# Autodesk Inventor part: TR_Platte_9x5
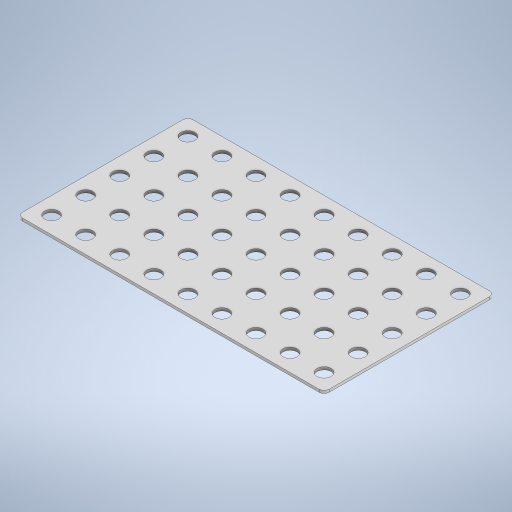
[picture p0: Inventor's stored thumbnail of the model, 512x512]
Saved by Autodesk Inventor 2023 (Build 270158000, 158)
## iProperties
Created: 2023-11
Part Number: TR_Platte_9x5
Material: Generisch
Document SubType Name: Modeling
Designer: Administrator
Density: 1 g/cm^3
Appearance: Vorgabe
Author: Administrator
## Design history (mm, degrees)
sketch "Skizze1"
  geometry: L1 (45, 25)-(-45, 25); L2 (-45, 25)-(-45, -25); L3 (-45, -25)-(45, -25); L4 (45, -25)-(45, 25); L5 (45, 25)-(-45, -25); L6 (-45, 25)-(45, -25); 1 further point
  constraints: 12 end point, 2 midpoint, 2 parallel, 1 horizontal, 1 perpendicular
  dimensions: "d0" = 90 distance of L3.end L2.end (computed from Lochx, Einheitsmaß); "d1" = 50 distance of L3.end L1.start (computed from Lochy, Einheitsmaß)
extrude "Extrusion1" new body sketch "Skizze1" distance "d2" = 0.8 (= Dicke); taper "d3" = 0 deg
sketch "Skizze2"
  geometry: L1 (45, -25)-(45, 25) reference; L2 (-45, -25)-(45, -25) reference; C1 r 2.075 at (40, -20); 1 further point
  constraints: 1 centre point
  dimensions: "d4" = 4.15 diameter of C1 (= 2 x Radius); "d5" = 5 distance from line of L1 C1.centre (= 0.5 x Einheitsmaß); "d6" = 5 distance from line of C1.centre L2 (= 0.5 x Einheitsmaß)
extrude "Extrusion2" cut sketch "Skizze2" extent not by distance; stored distance "d7" = 0; taper "d8" = 0 deg
fillet "Rundung1" dims "d15" = 1.5
node "Volumenkörper1"
pattern_linear "Rechteckige Anordnung1" dims "d11" = 10 (= Einheitsmaß), "d14" = 10 (= Einheitsmaß)
other parameters: "Einheitsmaß" = 10 [user parameter; used in 6 equation terms], "Radius" = 2.075 [user parameter; used in 1 equation term], "Fasen" = 0.5 [user parameter], "Dicke" = 0.8 [user parameter; used in 1 equation term], "Breitloch" = 2 [user parameter], "Langloch" = 32 [user parameter], "AchteckUmkreis" = 6 [user parameter], "DAchsAufnahme" = 4.1 [user parameter], "AchsDurchmesser" = 4 [user parameter], "AchsFase" = 0.5 [user parameter]
